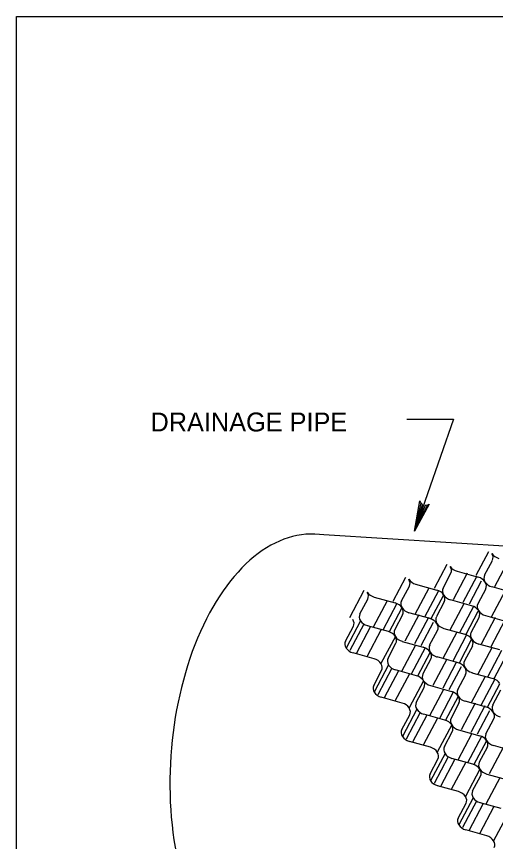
# Model space of a CAD drawing. Extents: x 638850 to 644908, y 297188 to 298900.
# Drawn here: x 639730.4 to 639806.4, y 297907.6 to 298038.5 of the extents above; entities that cross this region are included whole.
import ezdxf

# ---------------------------------------------------------------- set-up
doc = ezdxf.new("R2010")
doc.units = 0
doc.layers.add('1', color=7, linetype='Continuous')
doc.layers.add('2', color=7, linetype='Continuous')

msp = doc.modelspace()

# ---------------------------------------------------------------- linework, layer by layer
at = {"layer": '1'}
for p, q in [((639730.44, 297474.53), (639730.44, 298038.53)), ((639730.44, 298038.53), (640516.44, 298038.53)), ((639792.34, 297974.59), (639799.76, 297974.59)), ((639799.76, 297974.59), (639793.58, 297956.81)), ((639779.21, 297956.29), (639811.12, 297954.27))]:
    msp.add_line(p, q, dxfattribs=at)
msp.add_lwpolyline([(639795.64, 297960.97), (639795.27, 297960.92), (639793.58, 297956.81), (639795.64, 297960.97), (639795.91, 297961.13), (639793.58, 297956.81), (639794.83, 297961.07), (639794.57, 297961.33), (639793.58, 297956.81), (639794.45, 297961.64), (639794.57, 297961.33)], dxfattribs=at)
msp.add_ellipse((639775.71, 297919.52), major_axis=(2.32, 36.84), ratio=0.564762, start_param=6.226596, end_param=9.461585, dxfattribs=at)
at = {"layer": '2'}
for p, q in [((639805.32, 297953.57), (639803.32, 297949.77)), ((639798.73, 297951.52), (639796.72, 297947.72)), ((639804.7, 297949.85), (639805.95, 297952.2)), ((639808.5, 297952.19), (639806.29, 297948)), ((639798.11, 297947.8), (639799.35, 297950.15)), ((639801.91, 297950.14), (639799.7, 297945.95)), ((639800.36, 297950.47), (639803.7, 297949.53)), ((639792.14, 297949.47), (639790.13, 297945.67)), ((639803.45, 297949.71), (639801.24, 297945.52)), ((639804.18, 297948.92), (639802.24, 297945.23)), ((639785.54, 297947.42), (639783.26, 297943.1)), ((639791.51, 297945.75), (639792.76, 297948.1)), ((639795.85, 297947.81), (639793.64, 297943.62)), ((639793.76, 297948.42), (639797.1, 297947.48)), ((639797.39, 297947.38), (639795.17, 297943.19)), ((639804.88, 297947.67), (639803.64, 297945.31)), ((639807.97, 297947.37), (639805.76, 297943.18)), ((639809.23, 297947.05), (639805.89, 297947.98)), ((639784.92, 297943.7), (639786.16, 297946.06)), ((639787.17, 297946.37), (639790.51, 297945.44)), ((639798.12, 297946.59), (639796.18, 297942.91)), ((639789.25, 297945.76), (639787.04, 297941.57)), ((639790.79, 297945.33), (639788.58, 297941.14)), ((639798.29, 297945.62), (639797.05, 297943.26)), ((639801.38, 297945.32), (639799.17, 297941.13)), ((639802.63, 297945), (639799.3, 297945.93)), ((639802.92, 297944.89), (639800.71, 297940.7)), ((639791.53, 297944.54), (639789.58, 297940.86)), ((639791.7, 297943.57), (639790.45, 297941.21)), ((639794.25, 297943.55), (639792.04, 297939.36)), ((639796.04, 297942.95), (639792.7, 297943.88)), ((639803.65, 297944.1), (639801.71, 297940.42)), ((639804.83, 297943.44), (639808.17, 297942.51)), ((639785.01, 297942.61), (639782.73, 297938.28)), ((639785.54, 297942.09), (639783.31, 297937.87)), ((639795.79, 297943.13), (639793.58, 297938.93)), ((639796.53, 297942.33), (639794.58, 297938.65)), ((639802.58, 297940.77), (639803.82, 297943.13)), ((639806.38, 297943.11), (639804.17, 297938.92)), ((639807.92, 297942.69), (639805.71, 297938.49)), ((639782.64, 297939.37), (639783.88, 297941.73)), ((639786.59, 297941.7), (639784.31, 297937.37)), ((639788.29, 297941.22), (639786.01, 297936.9)), ((639789.45, 297940.9), (639786.11, 297941.83)), ((639795.98, 297938.72), (639797.23, 297941.08)), ((639800.31, 297940.79), (639798.1, 297936.6)), ((639798.23, 297941.39), (639801.57, 297940.46)), ((639790.54, 297940.12), (639788.26, 297935.8)), ((639801.85, 297940.36), (639799.64, 297936.17)), ((639802.59, 297939.57), (639800.64, 297935.88)), ((639789.39, 297936.67), (639790.64, 297939.03)), ((639793.72, 297938.74), (639791.51, 297934.55)), ((639791.64, 297939.34), (639794.98, 297938.41)), ((639795.26, 297938.31), (639793.05, 297934.12)), ((639802.76, 297938.59), (639801.51, 297936.24)), ((639805.85, 297938.3), (639803.63, 297934.11)), ((639807.1, 297937.97), (639803.76, 297938.9)), ((639787.17, 297936.57), (639783.83, 297937.51)), ((639796, 297937.52), (639794.05, 297933.83)), ((639800.51, 297935.92), (639797.17, 297936.86)), ((639807.39, 297937.87), (639805.17, 297933.68)), ((639808.12, 297937.08), (639806.18, 297933.39)), ((639789.48, 297935.59), (639787.2, 297931.26)), ((639796.17, 297936.54), (639794.92, 297934.19)), ((639798.72, 297936.53), (639796.51, 297932.34)), ((639800.26, 297936.1), (639798.05, 297931.91)), ((639787.11, 297932.35), (639788.35, 297934.71)), ((639790, 297935.06), (639787.78, 297930.84)), ((639791.06, 297934.67), (639788.78, 297930.35)), ((639793.92, 297933.87), (639790.58, 297934.81)), ((639801, 297935.31), (639799.05, 297931.63)), ((639802.7, 297934.37), (639806.04, 297933.44)), ((639792.76, 297934.2), (639790.48, 297929.87)), ((639795.01, 297933.1), (639792.73, 297928.77)), ((639800.45, 297931.7), (639801.7, 297934.06)), ((639804.78, 297933.76), (639802.57, 297929.57)), ((639806.32, 297933.33), (639804.11, 297929.14)), ((639793.86, 297929.65), (639795.1, 297932.01)), ((639798.19, 297931.71), (639795.98, 297927.53)), ((639796.11, 297932.32), (639799.45, 297931.39)), ((639807.06, 297932.54), (639805.11, 297928.86)), ((639791.63, 297929.55), (639788.29, 297930.48)), ((639799.73, 297931.29), (639797.52, 297927.1)), ((639800.46, 297930.5), (639798.52, 297926.81)), ((639807.23, 297931.57), (639805.98, 297929.21)), ((639800.63, 297929.52), (639799.39, 297927.16)), ((639803.19, 297929.51), (639800.98, 297925.32)), ((639804.98, 297928.9), (639801.64, 297929.83)), ((639804.73, 297929.08), (639802.52, 297924.89)), ((639791.57, 297925.33), (639792.82, 297927.68)), ((639793.95, 297928.56), (639791.67, 297924.24)), ((639794.47, 297928.04), (639792.24, 297923.82)), ((639798.38, 297926.85), (639795.04, 297927.78)), ((639805.46, 297928.29), (639803.52, 297924.6)), ((639795.53, 297927.65), (639793.25, 297923.32)), ((639797.23, 297927.17), (639794.95, 297922.85)), ((639804.92, 297924.67), (639806.16, 297927.03)), ((639799.48, 297926.07), (639797.2, 297921.75)), ((639800.58, 297925.29), (639803.92, 297924.36)), ((639798.33, 297922.63), (639799.57, 297924.98)), ((639802.66, 297924.69), (639800.45, 297920.5)), ((639804.2, 297924.26), (639801.99, 297920.07)), ((639796.1, 297922.52), (639792.76, 297923.46)), ((639804.94, 297923.47), (639802.99, 297919.78)), ((639805.1, 297922.5), (639803.86, 297920.14)), ((639807.66, 297922.48), (639805.45, 297918.29)), ((639809.45, 297921.87), (639806.11, 297922.81)), ((639798.42, 297921.54), (639796.14, 297917.21)), ((639796.05, 297918.3), (639797.29, 297920.66)), ((639798.94, 297921.02), (639796.72, 297916.79)), ((639800, 297920.62), (639797.72, 297916.3)), ((639801.7, 297920.15), (639799.42, 297915.82)), ((639802.85, 297919.83), (639799.51, 297920.76)), ((639803.95, 297919.05), (639801.67, 297914.72)), ((639802.79, 297915.6), (639804.04, 297917.96)), ((639807.13, 297917.66), (639804.92, 297913.47)), ((639805.05, 297918.27), (639808.38, 297917.34)), ((639800.57, 297915.5), (639797.23, 297916.43)), ((639800.51, 297911.28), (639801.76, 297913.63)), ((639802.89, 297914.51), (639800.6, 297910.19)), ((639803.41, 297913.99), (639801.18, 297909.77)), ((639804.47, 297913.6), (639802.18, 297909.27)), ((639807.32, 297912.8), (639803.98, 297913.73)), ((639806.17, 297913.12), (639803.89, 297908.8)), ((639808.42, 297912.03), (639806.13, 297907.7)), ((639805.04, 297908.48), (639801.7, 297909.41))]:
    msp.add_line(p, q, dxfattribs=at)
for centre, start_param, end_param in [((639804.5, 297952.87), 3.045062, 3.936083), ((639807.21, 297953.71), 0.794491, 1.685512), ((639797.91, 297950.82), 3.045062, 3.936083), ((639800.61, 297951.66), 0.794491, 1.685512), ((639791.32, 297948.77), 3.045062, 3.936083), ((639794.02, 297949.61), 0.794491, 1.685512), ((639803.44, 297948.34), 3.936083, 4.827105), ((639806.14, 297949.18), 6.186654, 7.077676), ((639806.14, 297949.18), 0.794491, 1.685512), ((639803.44, 297948.34), 3.045062, 3.936083), ((639796.85, 297946.29), 3.936083, 4.827105), ((639799.55, 297947.13), 6.186654, 7.077676), ((639784.72, 297946.73), 3.045062, 3.936083), ((639787.43, 297947.57), 0.794491, 1.685512), ((639796.85, 297946.29), 3.045062, 3.936083), ((639799.55, 297947.13), 0.794491, 1.685512), ((639790.25, 297944.24), 3.936083, 4.827105), ((639792.96, 297945.08), 6.186654, 7.077676), ((639802.38, 297943.8), 3.936083, 4.827105), ((639805.08, 297944.64), 6.186654, 7.077676), ((639786.36, 297943.03), 6.186654, 7.077676), ((639790.25, 297944.24), 3.045062, 3.936083), ((639792.96, 297945.08), 0.794491, 1.685512), ((639802.38, 297943.8), 3.045062, 3.936083), ((639805.08, 297944.64), 0.794491, 1.685512), ((639782.44, 297942.4), 3.045062, 3.936083), ((639786.36, 297943.03), 0.794491, 1.685512), ((639795.78, 297941.75), 3.936083, 4.827105), ((639798.49, 297942.59), 6.186654, 7.077676), ((639795.78, 297941.75), 3.045062, 3.936083), ((639798.49, 297942.59), 0.794491, 1.685512), ((639789.19, 297939.7), 3.936083, 4.827105), ((639791.89, 297940.54), 6.186654, 7.077676), ((639804.02, 297940.1), 6.186654, 7.077676), ((639789.19, 297939.7), 3.045062, 3.936083), ((639791.89, 297940.54), 0.794491, 1.685512), ((639801.32, 297939.26), 3.936083, 4.827105), ((639804.02, 297940.1), 0.794491, 1.685512), ((639801.32, 297939.26), 3.045062, 3.936083), ((639784.08, 297938.7), 6.186654, 7.077676), ((639784.08, 297938.7), 0.794491, 1.685512), ((639794.72, 297937.21), 3.936083, 4.827105), ((639797.43, 297938.05), 6.186654, 7.077676), ((639794.72, 297937.21), 3.045062, 3.936083), ((639797.43, 297938.05), 0.794491, 1.685512), ((639786.91, 297935.38), 3.936083, 4.827105), ((639786.91, 297935.38), 3.045062, 3.936083), ((639790.83, 297936), 6.186654, 7.077676), ((639790.83, 297936), 0.794491, 1.685512), ((639800.25, 297934.73), 3.936083, 4.827105), ((639802.96, 297935.57), 6.186654, 7.077676), ((639800.25, 297934.73), 3.045062, 3.936083), ((639802.96, 297935.57), 0.794491, 1.685512), ((639793.66, 297932.68), 3.936083, 4.827105), ((639796.36, 297933.52), 6.186654, 7.077676), ((639793.66, 297932.68), 3.045062, 3.936083), ((639796.36, 297933.52), 0.794491, 1.685512), ((639805.78, 297932.24), 3.936083, 4.827105), ((639788.55, 297931.68), 6.186654, 7.077676), ((639801.89, 297931.03), 6.186654, 7.077676), ((639788.55, 297931.68), 0.794491, 1.685512), ((639799.19, 297930.19), 3.936083, 4.827105), ((639799.19, 297930.19), 3.045062, 3.936083), ((639801.89, 297931.03), 0.794491, 1.685512), ((639791.38, 297928.35), 3.936083, 4.827105), ((639795.3, 297928.98), 6.186654, 7.077676), ((639807.43, 297928.54), 6.186654, 7.077676), ((639791.38, 297928.35), 3.045062, 3.936083), ((639795.3, 297928.98), 0.794491, 1.685512), ((639804.72, 297927.7), 3.936083, 4.827105), ((639804.72, 297927.7), 3.045062, 3.936083), ((639807.43, 297928.54), 0.794491, 1.685512), ((639798.13, 297925.65), 3.936083, 4.827105), ((639800.83, 297926.49), 6.186654, 7.077676), ((639793.02, 297924.66), 6.186654, 7.077676), ((639798.13, 297925.65), 3.045062, 3.936083), ((639800.83, 297926.49), 0.794491, 1.685512), ((639793.02, 297924.66), 0.794491, 1.685512), ((639803.66, 297923.17), 3.936083, 4.827105), ((639806.36, 297924.01), 6.186654, 7.077676), ((639795.85, 297921.33), 3.936083, 4.827105), ((639799.77, 297921.96), 6.186654, 7.077676), ((639806.36, 297924.01), 0.794491, 1.685512), ((639803.66, 297923.17), 3.045062, 3.936083), ((639795.85, 297921.33), 3.045062, 3.936083), ((639799.77, 297921.96), 0.794491, 1.685512), ((639802.6, 297918.63), 3.936083, 4.827105), ((639805.3, 297919.47), 6.186654, 7.077676), ((639802.6, 297918.63), 3.045062, 3.936083), ((639805.3, 297919.47), 0.794491, 1.685512), ((639797.49, 297917.63), 6.186654, 7.077676), ((639797.49, 297917.63), 0.794491, 1.685512), ((639800.31, 297914.3), 3.936083, 4.827105), ((639800.31, 297914.3), 3.045062, 3.936083), ((639804.24, 297914.93), 6.186654, 7.077676), ((639804.24, 297914.93), 0.794491, 1.685512), ((639801.96, 297910.61), 6.186654, 7.077676), ((639801.96, 297910.61), 0.794491, 1.685512), ((639804.78, 297907.28), 3.936083, 4.827105), ((639804.78, 297907.28), 3.045062, 3.936083)]:
    msp.add_ellipse(centre, major_axis=(-1.49, 0.56), ratio=0.764477, start_param=start_param, end_param=end_param, dxfattribs=at)

# ---------------------------------------------------------------- texts
at = {"layer": '1'}
msp.add_text('DRAINAGE PIPE', height=3, dxfattribs=at).set_placement((639751.7, 297972.66))

doc.saveas('drawing.dxf')
